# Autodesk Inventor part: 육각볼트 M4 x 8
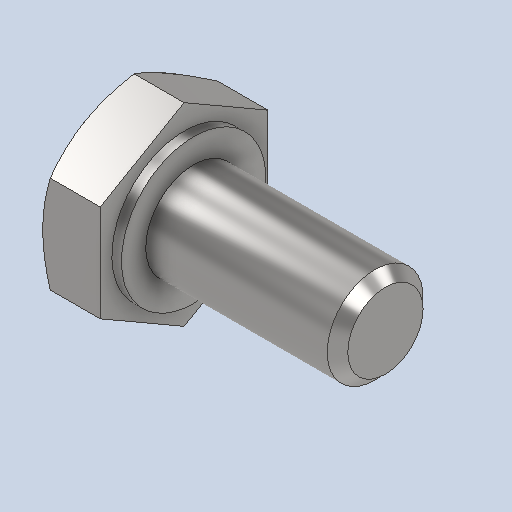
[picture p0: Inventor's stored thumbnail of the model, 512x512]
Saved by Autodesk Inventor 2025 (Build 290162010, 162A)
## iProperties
Created: 2024-07
Part Number: 육각볼트 M4 x 8
Material: 강철, 연강
Description: 6각 머리 나사
Document SubType Name: Modeling
Designer: 계정
Density: 7.86 g/cm^3
Appearance: 기본값
Author: jhkim
Sending System: Autodesk Inventor 2025
Preprocessor: ST-DEVELOPER v20
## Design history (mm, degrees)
feature "Solid1"
node "솔리드1"
